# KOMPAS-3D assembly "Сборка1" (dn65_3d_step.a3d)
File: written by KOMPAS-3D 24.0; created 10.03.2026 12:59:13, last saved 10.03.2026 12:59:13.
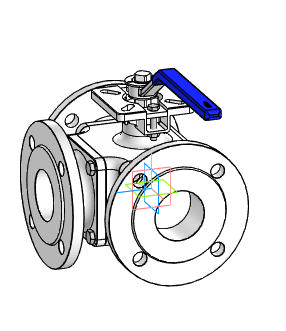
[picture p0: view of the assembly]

Document properties: Автор: R2D2; Полное имя файла: E:\Работа\Зайцев\BV3232P(4pc)-FP-3WL-F-ISO-H Кран шаровой DN.ru Ду15-100 Ру16\DN65\исходные материалы\dn65_3d_step.a3d

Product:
- Component [detail]: Деталь  | qty 1  | Автор: R2D2; source file: Деталь Деталь.m3d
- Component [detail]: Деталь1  | qty 1  | Автор: R2D2; source file: Деталь1 Деталь1.m3d
- Component [detail]: AS 1110 - M8 x 40  | qty 1  | Автор: R2D2; source file: AS 1110 - M8 x 40 AS 1110 - M8 x 40.m3d
- Component [detail]: AS 1110 - M8 x 40  | qty 1  | Комментарий: Болты и винты   шестигранные точные   метрические ISO; Автор: R2D2; additional columns: Сталь, мягкая; source file: AS 1110 - M8 x 40 AS 1110 - M8 x 40.m3d
- Component [detail]: ANSI B18.2.4.2M - M8x1,25 - 13  | designation ANSI B18.2.4.2M - M8x1,25  | qty 1  | Автор: R2D2; source file: ANSI B18.2.4.2M - M8x1,25 ANSI B18.2.4.2M - M8x1,25 - 13.m3d
- Component [detail]: ANSI B18.2.4.2M - M8x1,25 - 13  | designation ANSI B18.2.4.2M - M8x1,25  | qty 1  | Комментарий: Типы метрических   шестигранных гаек   2; Автор: R2D2; additional columns: Сталь, мягкая; source file: ANSI B18.2.4.2M - M8x1,25 ANSI B18.2.4.2M - M8x1,25 - 13.m3d
- Component [detail]: AS 1110 - M10 x 16  | qty 1  | Автор: R2D2; source file: AS 1110 - M10 x 16 AS 1110 - M10 x 16.m3d
- Component [detail]: AS 1110 - M10 x 16  | qty 11  | Комментарий: Болты и винты   шестигранные точные   метрические ISO; Автор: R2D2; additional columns: Сталь, мягкая; source file: AS 1110 - M10 x 16 AS 1110 - M10 x 16.m3d
- Part/product: Сборка1

Referenced files in E:\Работа\Зайцев\BV3232P(4pc)-FP-3WL-F-ISO-H Кран шаровой DN.ru Ду15-100 Ру16\DN65\исходные материалы\: Деталь Деталь.m3d, Деталь1 Деталь1.m3d, AS 1110 - M8 x 40 AS 1110 - M8 x 40.m3d, ANSI B18.2.4.2M - M8x1,25 ANSI B18.2.4.2M - M8x1,25 - 13.m3d, AS 1110 - M10 x 16 AS 1110 - M10 x 16.m3d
